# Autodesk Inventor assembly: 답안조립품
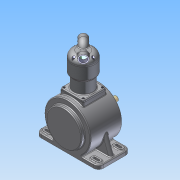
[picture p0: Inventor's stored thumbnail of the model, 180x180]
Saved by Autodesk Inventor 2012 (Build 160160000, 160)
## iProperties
Created: 2015-06
Part Number: 답안조립품
Document SubType Name: Assembly
Designer: Administrator
Author: Administrator
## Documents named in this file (15)
- C:\Documents and Settings\Administrator\바탕 화면\450605V1022\답안조립품.iam
- C:\Documents and Settings\Administrator\바탕 화면\450605V1022\1.본체.ipt
- C:\Documents and Settings\Administrator\바탕 화면\450605V1022\메인커버.ipt
- C:\Documents and Settings\Administrator\바탕 화면\450605V1022\베어링 6204.ipt
- C:\Documents and Settings\Administrator\바탕 화면\450605V1022\오일실.ipt
- C:\Documents and Settings\Administrator\바탕 화면\450605V1022\메인 크랭크 축-구동부.ipt
- C:\Documents and Settings\Administrator\바탕 화면\450605V1022\크랭크 서브축.ipt
- C:\Documents and Settings\Administrator\바탕 화면\450605V1022\실린더.ipt
- C:\Documents and Settings\Administrator\바탕 화면\450605V1022\실린더헤드.ipt
- C:\Documents and Settings\Administrator\바탕 화면\450605V1022\M4x0.7.ipt
- C:\Documents and Settings\Administrator\바탕 화면\450605V1022\M5x0.8.ipt
- C:\Documents and Settings\Administrator\바탕 화면\450605V1022\베어링 NA 4902.ipt
- C:\Documents and Settings\Administrator\바탕 화면\450605V1022\커넥팅 로드.ipt
- C:\Documents and Settings\Administrator\바탕 화면\450605V1022\피스톤.ipt
- C:\Documents and Settings\Administrator\바탕 화면\450605V1022\피스톤 핀.ipt
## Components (15 placed, 5 different names)
1. 1.본체:1
2. 피스톤:1
3. 피스톤 핀:1
4. M4x0.7:1
5. M4x0.7:3
6. M4x0.7:4
7. M4x0.7:5
8. M4x0.7:2
9. M4x0.7:6
10. M4x0.7:7
11. M4x0.7:8
12. M5x0.8:1
13. M5x0.8:2
14. M5x0.8:3
15. M5x0.8:4
